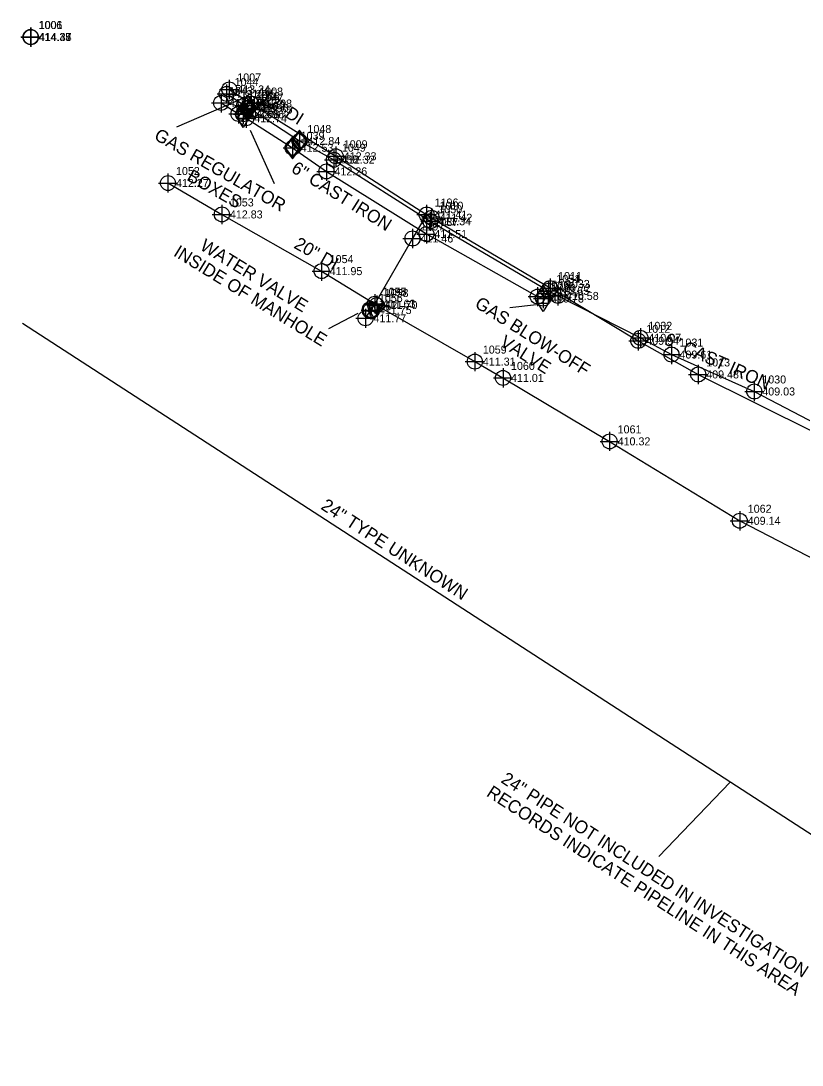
# Model space of a CAD drawing. Extents: x 2024146 to 2025516, y 819906 to 820765.
# Drawn here: x 2024145.9 to 2024389.9, y 820438.4 to 820764.6 of the extents above; entities that cross this region are included whole.
import ezdxf

# ---------------------------------------------------------------- set-up
doc = ezdxf.new("R2010")
doc.units = 0
for name, color, linetype in [('Prop Approach Slab', 7, 'Continuous'), ('Prop Conc 2ft 6in Curb and Gutter', 7, 'Continuous'), ('Prop Conc 4in Sidewalk', 7, 'Continuous'), ('Prop DSN Text', 7, 'Continuous'), ('Prop EOT', 7, 'Continuous'), ('Prop Horizontal Alignment', 7, 'Continuous'), ('Prop Horizontal Alignment Station Label', 7, 'Continuous'), ('Prop Horizontal Alignment Tick Small', 7, 'Continuous'), ('Prop Lane Lines', 7, 'Continuous'), ('Prop Roadway Bridge', 7, 'Continuous'), ('Prop Superelevation  Arrow CELL', 7, 'Continuous'), ('Sheet Block Revision CELL', 7, 'Continuous'), ('Sheet Data Field CELL', 7, 'Continuous'), ('Sheet Layout Plan Border', 7, 'Continuous'), ('Sheet Layout Profile Border Port 2', 7, 'Continuous'), ('Sheet Plan And Profile CELL', 7, 'Continuous'), ('Sheet Profile Grid Minor CELL', 7, 'Continuous')]:
    doc.layers.add(name, color=color, linetype=linetype)

# ---------------------------------------------------------------- blocks, each defined once
blk = doc.blocks.new('EXIST UTILITIES GAS VALVE')
at = {"layer": 'Prop Roadway Bridge'}
blk.add_line((0, 0), (0, 0), dxfattribs=at)
blk.add_lwpolyline([(0, 0.0683), (-0.0508, 0), (0, -0.0683), (0.0508, 0), (0, 0.0683)], dxfattribs=at)
blk.add_lwpolyline([(0.0458, 0), (0, 0.0615), (-0.0458, 0), (0, -0.0615)], close=True, dxfattribs=at)
blk = doc.blocks.new('EXIST UTILITIES GAS METER')
at = {"layer": 'Prop Horizontal Alignment'}
blk.add_line((0, 0), (0, 0), dxfattribs=at)
for points in [[(-0.05075, 0), (0, 0.08225), (0.05075, 0), (0, -0.08225), (-0.05075, 0)], [(-0.0315, 0.03075), (0.0315, 0.03075), (0.0315, -0.0315), (-0.0315, -0.0315), (-0.0315, 0.03075)]]:
    blk.add_lwpolyline(points, dxfattribs=at)
blk = doc.blocks.new('EXIST UTILITIES WATER MANHOLE')
at = {"layer": 'Prop Horizontal Alignment Tick Small'}
blk.add_line((0, 0), (0, 0), dxfattribs=at)
blk.add_circle((0, 0.0001), 0.0539, dxfattribs=at)
blk.add_text('W', height=0.07, dxfattribs=at).set_placement((-0.027, -0.035))

msp = doc.modelspace()

# ---------------------------------------------------------------- linework, layer by layer
at = {"layer": 'Prop Conc 2ft 6in Curb and Gutter'}
msp.add_lwpolyline([(2024251.11, 820673.13), (2024241.96, 820668.34)], dxfattribs=at)
at = {"layer": 'Prop EOT'}
for points in [[(2024215.43, 820740.43), (2024194.5, 820731.41)], [(2024217.52, 820730.43), (2024225, 820713.79)], [(2024306.9, 820675.93), (2024298.66, 820674.96)]]:
    msp.add_lwpolyline(points, dxfattribs=at)
at = {"layer": 'Prop Lane Lines'}
msp.add_lwpolyline([(2024146.4, 820670.11), (2024566.33, 820397.9)], dxfattribs=at)
at = {"layer": 'Prop Superelevation  Arrow CELL'}
msp.add_lwpolyline([(2024367.44, 820526.81), (2024345.2, 820503.57)], dxfattribs=at)
at = {"layer": 'Sheet Layout Plan Border'}
for points in [[(2024148.91, 820762.56), (2024148.91, 820759.56)], [(2024149.01, 820762.54), (2024149.01, 820759.54)], [(2024149.06, 820762.51), (2024149.06, 820759.51)], [(2024145.91, 820759.56), (2024148.91, 820759.56)], [(2024146.01, 820759.54), (2024149.01, 820759.54)], [(2024146.06, 820759.51), (2024149.06, 820759.51)], [(2024148.91, 820759.56), (2024151.91, 820759.56)], [(2024148.91, 820759.56), (2024148.91, 820756.56)], [(2024149.01, 820759.54), (2024152.01, 820759.54)], [(2024149.01, 820759.54), (2024149.01, 820756.54)], [(2024149.06, 820759.51), (2024152.06, 820759.51)], [(2024149.06, 820759.51), (2024149.06, 820756.51)], [(2024207.99, 820743.18), (2024210.99, 820743.18)], [(2024210.17, 820744.77), (2024210.17, 820741.77)], [(2024210.99, 820746.18), (2024210.99, 820743.18)], [(2024210.99, 820743.18), (2024213.99, 820743.18)], [(2024210.99, 820743.18), (2024210.99, 820740.18)], [(2024207.17, 820741.77), (2024210.17, 820741.77)], [(2024208.43, 820741.96), (2024208.43, 820738.96)], [(2024210.17, 820741.77), (2024213.17, 820741.77)], [(2024210.17, 820741.77), (2024210.17, 820738.77)], [(2024215.65, 820741.14), (2024215.65, 820738.14)], [(2024216.71, 820740.37), (2024216.71, 820737.37)], [(2024217.85, 820741.77), (2024217.85, 820738.77)], [(2024217.99, 820739.88), (2024217.99, 820736.88)], [(2024205.43, 820738.96), (2024208.43, 820738.96)], [(2024208.43, 820738.96), (2024211.43, 820738.96)], [(2024208.43, 820738.96), (2024208.43, 820735.96)], [(2024212.65, 820738.14), (2024215.65, 820738.14)], [(2024213.71, 820737.37), (2024216.71, 820737.37)], [(2024213.87, 820738.54), (2024213.87, 820735.54)], [(2024214.85, 820738.77), (2024217.85, 820738.77)], [(2024214.99, 820736.88), (2024217.99, 820736.88)], [(2024215.34, 820738.42), (2024215.34, 820735.42)], [(2024215.65, 820738.14), (2024218.65, 820738.14)], [(2024215.65, 820738.14), (2024215.65, 820735.14)], [(2024216.29, 820737.16), (2024216.29, 820734.16)], [(2024216.71, 820737.37), (2024219.71, 820737.37)], [(2024216.71, 820737.37), (2024216.71, 820734.37)], [(2024217.85, 820738.77), (2024220.85, 820738.77)], [(2024217.85, 820738.77), (2024217.85, 820735.77)], [(2024217.99, 820736.88), (2024220.99, 820736.88)], [(2024217.99, 820736.88), (2024217.99, 820733.88)], [(2024210.87, 820735.54), (2024213.87, 820735.54)], [(2024212.34, 820735.42), (2024215.34, 820735.42)], [(2024213.29, 820734.16), (2024216.29, 820734.16)], [(2024213.87, 820735.54), (2024216.87, 820735.54)], [(2024213.87, 820735.54), (2024213.87, 820732.54)], [(2024215.34, 820735.42), (2024218.34, 820735.42)], [(2024215.34, 820735.42), (2024215.34, 820732.42)], [(2024216.29, 820734.16), (2024219.29, 820734.16)], [(2024216.29, 820734.16), (2024216.29, 820731.16)], [(2024232.91, 820730.07), (2024232.91, 820727.07)], [(2024229.91, 820727.07), (2024232.91, 820727.07)], [(2024230.78, 820727.95), (2024230.78, 820724.95)], [(2024232.91, 820727.07), (2024235.91, 820727.07)], [(2024232.91, 820727.07), (2024232.91, 820724.07)], [(2024227.78, 820724.95), (2024230.78, 820724.95)], [(2024230.78, 820724.95), (2024233.78, 820724.95)], [(2024230.78, 820724.95), (2024230.78, 820721.95)], [(2024243.68, 820724.23), (2024243.68, 820721.23)], [(2024244.24, 820725.3), (2024244.24, 820722.3)], [(2024240.68, 820721.23), (2024243.68, 820721.23)], [(2024241.24, 820722.3), (2024244.24, 820722.3)], [(2024241.34, 820720.58), (2024241.34, 820717.58)], [(2024243.68, 820721.23), (2024246.68, 820721.23)], [(2024243.68, 820721.23), (2024243.68, 820718.23)], [(2024244.24, 820722.3), (2024247.24, 820722.3)], [(2024244.24, 820722.3), (2024244.24, 820719.3)], [(2024191.85, 820716.94), (2024191.85, 820713.94)], [(2024238.34, 820717.58), (2024241.34, 820717.58)], [(2024241.34, 820717.58), (2024244.34, 820717.58)], [(2024241.34, 820717.58), (2024241.34, 820714.58)], [(2024188.85, 820713.94), (2024191.85, 820713.94)], [(2024191.85, 820713.94), (2024194.85, 820713.94)], [(2024191.85, 820713.94), (2024191.85, 820710.94)], [(2024208.68, 820707.13), (2024208.68, 820704.13)], [(2024272.62, 820707.1), (2024272.62, 820704.1)], [(2024205.68, 820704.13), (2024208.68, 820704.13)], [(2024208.68, 820704.13), (2024211.68, 820704.13)], [(2024208.68, 820704.13), (2024208.68, 820701.13)], [(2024269.62, 820704.1), (2024272.62, 820704.1)], [(2024272.62, 820704.1), (2024275.62, 820704.1)], [(2024272.62, 820704.1), (2024272.62, 820701.1)], [(2024273.78, 820704.99), (2024273.78, 820701.99)], [(2024274.16, 820706.1), (2024274.16, 820703.1)], [(2024270.78, 820701.99), (2024273.78, 820701.99)], [(2024271.16, 820703.1), (2024274.16, 820703.1)], [(2024272.55, 820701.01), (2024272.55, 820698.01)], [(2024273.78, 820701.99), (2024276.78, 820701.99)], [(2024273.78, 820701.99), (2024273.78, 820698.99)], [(2024274.16, 820703.1), (2024277.16, 820703.1)], [(2024274.16, 820703.1), (2024274.16, 820700.1)], [(2024268.22, 820699.62), (2024268.22, 820696.62)], [(2024269.55, 820698.01), (2024272.55, 820698.01)], [(2024272.55, 820698.01), (2024275.55, 820698.01)], [(2024272.55, 820698.01), (2024272.55, 820695.01)], [(2024265.22, 820696.62), (2024268.22, 820696.62)], [(2024268.22, 820696.62), (2024271.22, 820696.62)], [(2024268.22, 820696.62), (2024268.22, 820693.62)], [(2024239.83, 820689.42), (2024239.83, 820686.42)], [(2024236.83, 820686.42), (2024239.83, 820686.42)], [(2024239.83, 820686.42), (2024242.83, 820686.42)], [(2024239.83, 820686.42), (2024239.83, 820683.42)], [(2024307.29, 820681.45), (2024307.29, 820678.45)], [(2024308.18, 820681.14), (2024311.18, 820681.14)], [(2024310.64, 820683.27), (2024310.64, 820680.27)], [(2024310.65, 820683.27), (2024310.65, 820680.27)], [(2024311.18, 820684.14), (2024311.18, 820681.14)], [(2024311.18, 820681.14), (2024314.18, 820681.14)], [(2024311.18, 820681.14), (2024311.18, 820678.14)], [(2024313.64, 820681.67), (2024313.64, 820678.67)], [(2024256.4, 820679.24), (2024256.4, 820676.24)], [(2024256.4, 820679.23), (2024256.4, 820676.23)], [(2024257.03, 820678.83), (2024257.03, 820675.83)], [(2024304.29, 820678.45), (2024307.29, 820678.45)], [(2024306.02, 820677.86), (2024309.02, 820677.86)], [(2024307.29, 820678.45), (2024310.29, 820678.45)], [(2024307.29, 820678.45), (2024307.29, 820675.45)], [(2024307.64, 820680.27), (2024310.64, 820680.27)], [(2024307.65, 820680.27), (2024310.65, 820680.27)], [(2024309.02, 820680.86), (2024309.02, 820677.86)], [(2024309.02, 820677.86), (2024312.02, 820677.86)], [(2024309.02, 820677.86), (2024309.02, 820674.86)], [(2024310.64, 820680.27), (2024313.64, 820680.27)], [(2024310.64, 820680.27), (2024310.64, 820677.27)], [(2024310.64, 820678.67), (2024313.64, 820678.67)], [(2024310.65, 820680.27), (2024313.65, 820680.27)], [(2024310.65, 820680.27), (2024310.65, 820677.27)], [(2024313.64, 820678.67), (2024316.64, 820678.67)], [(2024313.64, 820678.67), (2024313.64, 820675.67)], [(2024253.4, 820676.24), (2024256.4, 820676.24)], [(2024253.4, 820676.23), (2024256.4, 820676.23)], [(2024253.53, 820674.68), (2024253.53, 820671.68)], [(2024254.03, 820675.83), (2024257.03, 820675.83)], [(2024255.21, 820677.26), (2024255.21, 820674.26)], [(2024256.4, 820676.24), (2024259.4, 820676.24)], [(2024256.4, 820676.24), (2024256.4, 820673.24)], [(2024256.4, 820676.23), (2024259.4, 820676.23)], [(2024256.4, 820676.23), (2024256.4, 820673.23)], [(2024257.03, 820675.83), (2024260.03, 820675.83)], [(2024257.03, 820675.83), (2024257.03, 820672.83)], [(2024250.53, 820671.68), (2024253.53, 820671.68)], [(2024252.21, 820674.26), (2024255.21, 820674.26)], [(2024253.53, 820671.68), (2024256.53, 820671.68)], [(2024253.53, 820671.68), (2024253.53, 820668.68)], [(2024255.21, 820674.26), (2024258.21, 820674.26)], [(2024255.21, 820674.26), (2024255.21, 820671.26)], [(2024339.39, 820668.59), (2024339.39, 820665.59)], [(2024335.74, 820664.65), (2024338.74, 820664.65)], [(2024336.39, 820665.59), (2024339.39, 820665.59)], [(2024338.74, 820667.65), (2024338.74, 820664.65)], [(2024338.74, 820664.65), (2024341.74, 820664.65)], [(2024338.74, 820664.65), (2024338.74, 820661.65)], [(2024339.39, 820665.59), (2024342.39, 820665.59)], [(2024339.39, 820665.59), (2024339.39, 820662.59)], [(2024349.1, 820663.35), (2024349.1, 820660.35)], [(2024284.68, 820658.15), (2024287.68, 820658.15)], [(2024287.68, 820661.15), (2024287.68, 820658.15)], [(2024287.68, 820658.15), (2024290.68, 820658.15)], [(2024287.68, 820658.15), (2024287.68, 820655.15)], [(2024346.1, 820660.35), (2024349.1, 820660.35)], [(2024349.1, 820660.35), (2024352.1, 820660.35)], [(2024349.1, 820660.35), (2024349.1, 820657.35)], [(2024296.48, 820656.06), (2024296.48, 820653.06)], [(2024357.45, 820657.14), (2024357.45, 820654.14)], [(2024293.48, 820653.06), (2024296.48, 820653.06)], [(2024296.48, 820653.06), (2024299.48, 820653.06)], [(2024296.48, 820653.06), (2024296.48, 820650.06)], [(2024354.45, 820654.14), (2024357.45, 820654.14)], [(2024357.45, 820654.14), (2024360.45, 820654.14)], [(2024357.45, 820654.14), (2024357.45, 820651.14)], [(2024374.96, 820651.82), (2024374.96, 820648.82)], [(2024371.96, 820648.82), (2024374.96, 820648.82)], [(2024374.96, 820648.82), (2024377.96, 820648.82)], [(2024374.96, 820648.82), (2024374.96, 820645.82)], [(2024329.78, 820636.23), (2024329.78, 820633.23)], [(2024326.78, 820633.23), (2024329.78, 820633.23)], [(2024329.78, 820633.23), (2024332.78, 820633.23)], [(2024329.78, 820633.23), (2024329.78, 820630.23)], [(2024370.42, 820611.43), (2024370.42, 820608.43)], [(2024367.42, 820608.43), (2024370.42, 820608.43)], [(2024370.42, 820608.43), (2024373.42, 820608.43)], [(2024370.42, 820608.43), (2024370.42, 820605.43)]]:
    msp.add_lwpolyline(points, dxfattribs=at)
for centre in [(2024148.91, 820759.56), (2024149.01, 820759.54), (2024149.06, 820759.51), (2024210.17, 820741.77), (2024210.99, 820743.18), (2024208.43, 820738.96), (2024215.65, 820738.14), (2024216.71, 820737.37), (2024217.85, 820738.77), (2024213.87, 820735.54), (2024215.34, 820735.42), (2024216.29, 820734.16), (2024217.99, 820736.88), (2024230.78, 820724.95), (2024232.91, 820727.07), (2024243.68, 820721.23), (2024244.24, 820722.3), (2024241.34, 820717.58), (2024191.85, 820713.94), (2024208.68, 820704.13), (2024272.62, 820704.1), (2024273.78, 820701.99), (2024274.16, 820703.1), (2024268.22, 820696.62), (2024272.55, 820698.01), (2024239.83, 820686.42), (2024310.64, 820680.27), (2024310.65, 820680.27), (2024311.18, 820681.14), (2024313.64, 820678.67), (2024256.4, 820676.23), (2024256.4, 820676.24), (2024257.03, 820675.83), (2024307.29, 820678.45), (2024309.02, 820677.86), (2024255.21, 820674.26), (2024253.53, 820671.68), (2024339.39, 820665.59), (2024338.74, 820664.65), (2024349.1, 820660.35), (2024287.68, 820658.15), (2024296.48, 820653.06), (2024357.45, 820654.14), (2024374.96, 820648.82), (2024329.78, 820633.23), (2024370.42, 820608.43)]:
    msp.add_circle(centre, 2.34, dxfattribs=at)
at = {"layer": 'Sheet Plan And Profile CELL'}
for points in [[(2024210.98, 820743.19), (2024217.84, 820738.78), (2024244.24, 820722.31), (2024274.15, 820703.11), (2024311.17, 820681.15), (2024338.73, 820664.66), (2024357.44, 820654.15), (2024394.04, 820635.87), (2024420.76, 820619.83), (2024437.14, 820610.11), (2024452.82, 820602.18), (2024468.13, 820596.73), (2024507.66, 820573.2), (2024538.06, 820555.55), (2024559.18, 820542.37)], [(2024191.85, 820713.95), (2024208.67, 820704.14), (2024239.83, 820686.43), (2024256.4, 820676.24), (2024257.02, 820675.83), (2024287.67, 820658.15), (2024296.47, 820653.07), (2024329.77, 820633.23), (2024370.42, 820608.44), (2024394.34, 820596.06), (2024434.92, 820573.58), (2024468.18, 820554.9), (2024505.43, 820535.43), (2024535.14, 820520.96), (2024552.3, 820514.21)], [(2024272.62, 820704.1), (2024268.22, 820696.62), (2024256.4, 820676.24)], [(2024253.53, 820671.69), (2024255.2, 820674.26), (2024256.4, 820676.24)]]:
    msp.add_lwpolyline(points, dxfattribs=at)
at = {"layer": 'Sheet Profile Grid Minor CELL'}
for points in [[(2024217.98, 820736.88), (2024216.7, 820737.37), (2024215.64, 820738.15), (2024210.17, 820741.77)], [(2024208.42, 820738.96), (2024213.86, 820735.55), (2024215.34, 820735.42), (2024216.28, 820734.16), (2024230.78, 820724.95), (2024241.33, 820717.59), (2024272.55, 820698.02), (2024307.28, 820678.45), (2024309.02, 820677.87), (2024310.64, 820680.27)], [(2024217.98, 820736.88), (2024232.9, 820727.07), (2024243.67, 820721.23), (2024273.78, 820702), (2024310.64, 820680.27)], [(2024310.64, 820680.27), (2024313.64, 820678.67), (2024339.38, 820665.59), (2024349.09, 820660.35), (2024374.95, 820648.82), (2024408.83, 820631.1), (2024438.84, 820612.69), (2024467.31, 820595.36), (2024506.92, 820572.41), (2024537.38, 820554.46), (2024558.37, 820541.47)]]:
    msp.add_lwpolyline(points, dxfattribs=at)

# ---------------------------------------------------------------- block references
at = {"layer": 'Prop Horizontal Alignment', "xscale": 50, "yscale": 50}
for p in [(2024216.7, 820737.37), (2024215.34, 820735.42), (2024309.02, 820677.87)]:
    msp.add_blockref('EXIST UTILITIES GAS METER', p, dxfattribs=at)
at = {"layer": 'Prop Horizontal Alignment Tick Small', "xscale": 50, "yscale": 50}
msp.add_blockref('EXIST UTILITIES WATER MANHOLE', (2024255.2, 820674.26), dxfattribs=at)
at = {"layer": 'Prop Roadway Bridge', "xscale": 50, "yscale": 50}
for p in [(2024232.9, 820727.07), (2024230.78, 820724.95)]:
    msp.add_blockref('EXIST UTILITIES GAS VALVE', p, dxfattribs=at)

# ---------------------------------------------------------------- texts
at = {"layer": 'Prop Approach Slab'}
for s, p in [('INSIDE OF MANHOLE', (2024193.3, 820691.38)), ('WATER VALVE ', (2024201.55, 820693.34))]:
    msp.add_text(s, height=4, rotation=328.4013, dxfattribs=at).set_placement(p)
at = {"layer": 'Prop Conc 4in Sidewalk'}
for rotation, p in [(327.9149, (2024230.03, 820717.59)), (335.9691, (2024346.45, 820663.72))]:
    msp.add_text('6" CAST IRON', height=4, rotation=rotation, dxfattribs=at).set_placement(p)
at = {"layer": 'Prop DSN Text'}
for s, p in [('24" TYPE UNKNOWN', (2024239.31, 820612.27)), ('24" PIPE NOT INCLUDED IN INVESTIGATION', (2024295.56, 820526.85)), ('RECORDS INDICATE PIPELINE IN THIS AREA', (2024291.05, 820522.63))]:
    msp.add_text(s, height=4, rotation=327.0479, dxfattribs=at).set_placement(p)
at = {"layer": 'Prop Horizontal Alignment Station Label'}
for s, rotation, p in [('GAS REGULATOR', 330.1359, (2024187.22, 820727.78)), ('BOXES', 330.1359, (2024197.43, 820715)), ('GAS BLOW-OFF', 327.7648, (2024287.37, 820675.34)), ('VALVE', 327.7648, (2024295.21, 820663.3))]:
    msp.add_text(s, height=4, rotation=rotation, dxfattribs=at).set_placement(p)
at = {"layer": 'Sheet Block Revision CELL'}
for s, p in [('1006', (2024151.41, 820762.06)), ('1001', (2024151.51, 820762.04)), ('1', (2024151.56, 820762.02)), ('1044', (2024212.67, 820744.27)), ('1007', (2024213.49, 820745.68)), ('1043', (2024210.93, 820741.46)), ('1045', (2024218.15, 820740.64)), ('1008', (2024220.35, 820741.27)), ('1042', (2024216.37, 820738.04)), ('1041', (2024217.84, 820737.92)), ('1046', (2024219.21, 820739.87)), ('1047', (2024220.49, 820739.38)), ('1040', (2024218.79, 820736.66)), ('1039', (2024233.28, 820727.45)), ('1048', (2024235.41, 820729.57)), ('1009', (2024246.74, 820724.8)), ('1049', (2024246.18, 820723.73)), ('1038', (2024243.84, 820720.08)), ('1052', (2024194.35, 820716.44)), ('1053', (2024211.18, 820706.63)), ('1196', (2024275.12, 820706.6)), ('1010', (2024276.66, 820705.6)), ('1050', (2024276.28, 820704.49)), ('1197', (2024270.72, 820699.12)), ('1037', (2024275.05, 820700.51)), ('1054', (2024242.33, 820688.92)), ('1051', (2024313.14, 820682.77)), ('1034', (2024313.15, 820682.77)), ('1011', (2024313.68, 820683.64)), ('1198', (2024258.9, 820678.73)), ('1055', (2024258.9, 820678.74)), ('1036', (2024309.79, 820680.95)), ('1035', (2024311.52, 820680.36)), ('1033', (2024316.14, 820681.17)), ('1056', (2024257.71, 820676.76)), ('1058', (2024259.53, 820678.33)), ('1057', (2024256.03, 820674.18)), ('1012', (2024341.24, 820667.15)), ('1032', (2024341.89, 820668.09)), ('1031', (2024351.6, 820662.85)), ('1059', (2024290.18, 820660.65)), ('1013', (2024359.95, 820656.64)), ('1060', (2024298.98, 820655.56)), ('1030', (2024377.46, 820651.32)), ('1061', (2024332.28, 820635.73)), ('1062', (2024372.92, 820610.93))]:
    msp.add_text(s, height=2.5, dxfattribs=at).set_placement(p)
at = {"layer": 'Sheet Data Field CELL'}
for s, rotation, p in [('12" DI', 328.0371, (2024220.17, 820739.68)), ('20" DI', 330.3855, (2024230.89, 820693.81))]:
    msp.add_text(s, height=4, rotation=rotation, dxfattribs=at).set_placement(p)
at = {"layer": 'Sheet Layout Profile Border Port 2'}
for s, p in [('414.35', (2024151.41, 820758.31)), ('414.37', (2024151.51, 820758.29)), ('414.44', (2024151.56, 820758.27)), ('413.22', (2024212.67, 820740.52)), ('413.24', (2024213.49, 820741.93)), ('413.16', (2024210.93, 820737.71)), ('412.98', (2024220.35, 820737.52)), ('412.88', (2024216.37, 820734.29)), ('412.96', (2024217.84, 820734.17)), ('412.80', (2024218.15, 820736.89)), ('412.96', (2024219.21, 820736.12)), ('412.65', (2024220.49, 820735.63)), ('412.74', (2024218.79, 820732.91)), ('412.84', (2024235.41, 820725.82)), ('412.53', (2024233.28, 820723.7)), ('412.33', (2024246.74, 820721.05)), ('412.32', (2024246.18, 820719.98)), ('412.26', (2024243.84, 820716.33)), ('412.27', (2024194.35, 820712.69)), ('412.83', (2024211.18, 820702.88)), ('411.41', (2024275.12, 820702.85)), ('411.42', (2024276.66, 820701.85)), ('411.34', (2024276.28, 820700.74)), ('411.46', (2024270.72, 820695.37)), ('411.51', (2024275.05, 820696.76)), ('411.95', (2024242.33, 820685.17)), ('410.65', (2024313.14, 820679.02)), ('410.65', (2024313.15, 820679.02)), ('410.72', (2024313.68, 820679.89)), ('410.77', (2024309.79, 820677.2)), ('410.78', (2024311.52, 820676.61)), ('410.58', (2024316.14, 820677.42)), ('411.75', (2024257.71, 820673.01)), ('411.61', (2024258.9, 820674.98)), ('411.63', (2024258.9, 820674.99)), ('411.70', (2024259.53, 820674.58)), ('411.77', (2024256.03, 820670.43)), ('409.94', (2024341.24, 820663.4)), ('410.07', (2024341.89, 820664.34)), ('409.61', (2024351.6, 820659.1)), ('411.31', (2024290.18, 820656.9)), ('409.48', (2024359.95, 820652.89)), ('411.01', (2024298.98, 820651.81)), ('409.03', (2024377.46, 820647.57)), ('410.32', (2024332.28, 820631.98)), ('409.14', (2024372.92, 820607.18))]:
    msp.add_text(s, height=2.5, dxfattribs=at).set_placement(p)

doc.saveas('drawing.dxf')
